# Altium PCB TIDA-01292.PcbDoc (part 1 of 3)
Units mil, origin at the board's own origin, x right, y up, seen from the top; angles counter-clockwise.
Board outline 6102.36 x 3543.31 mil, 2 copper layers (Top Layer, Bottom Layer), stack 64.8 mil thick; 118 components, 43 nets, 376 pads, 3910 vias.
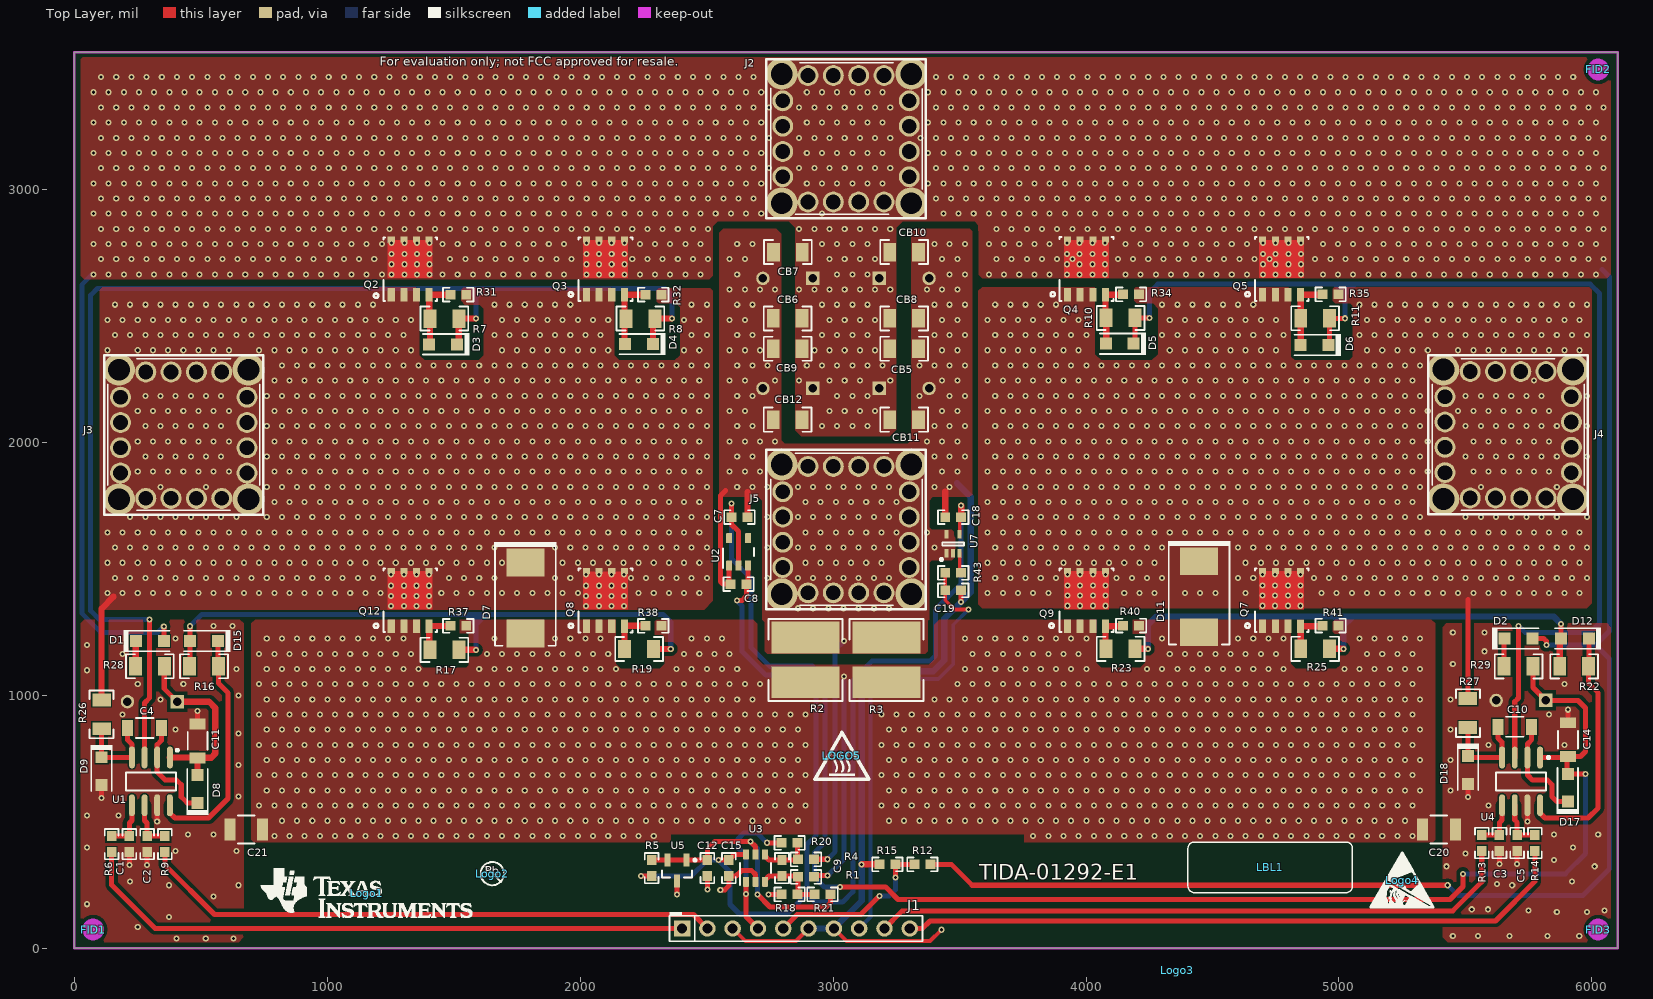
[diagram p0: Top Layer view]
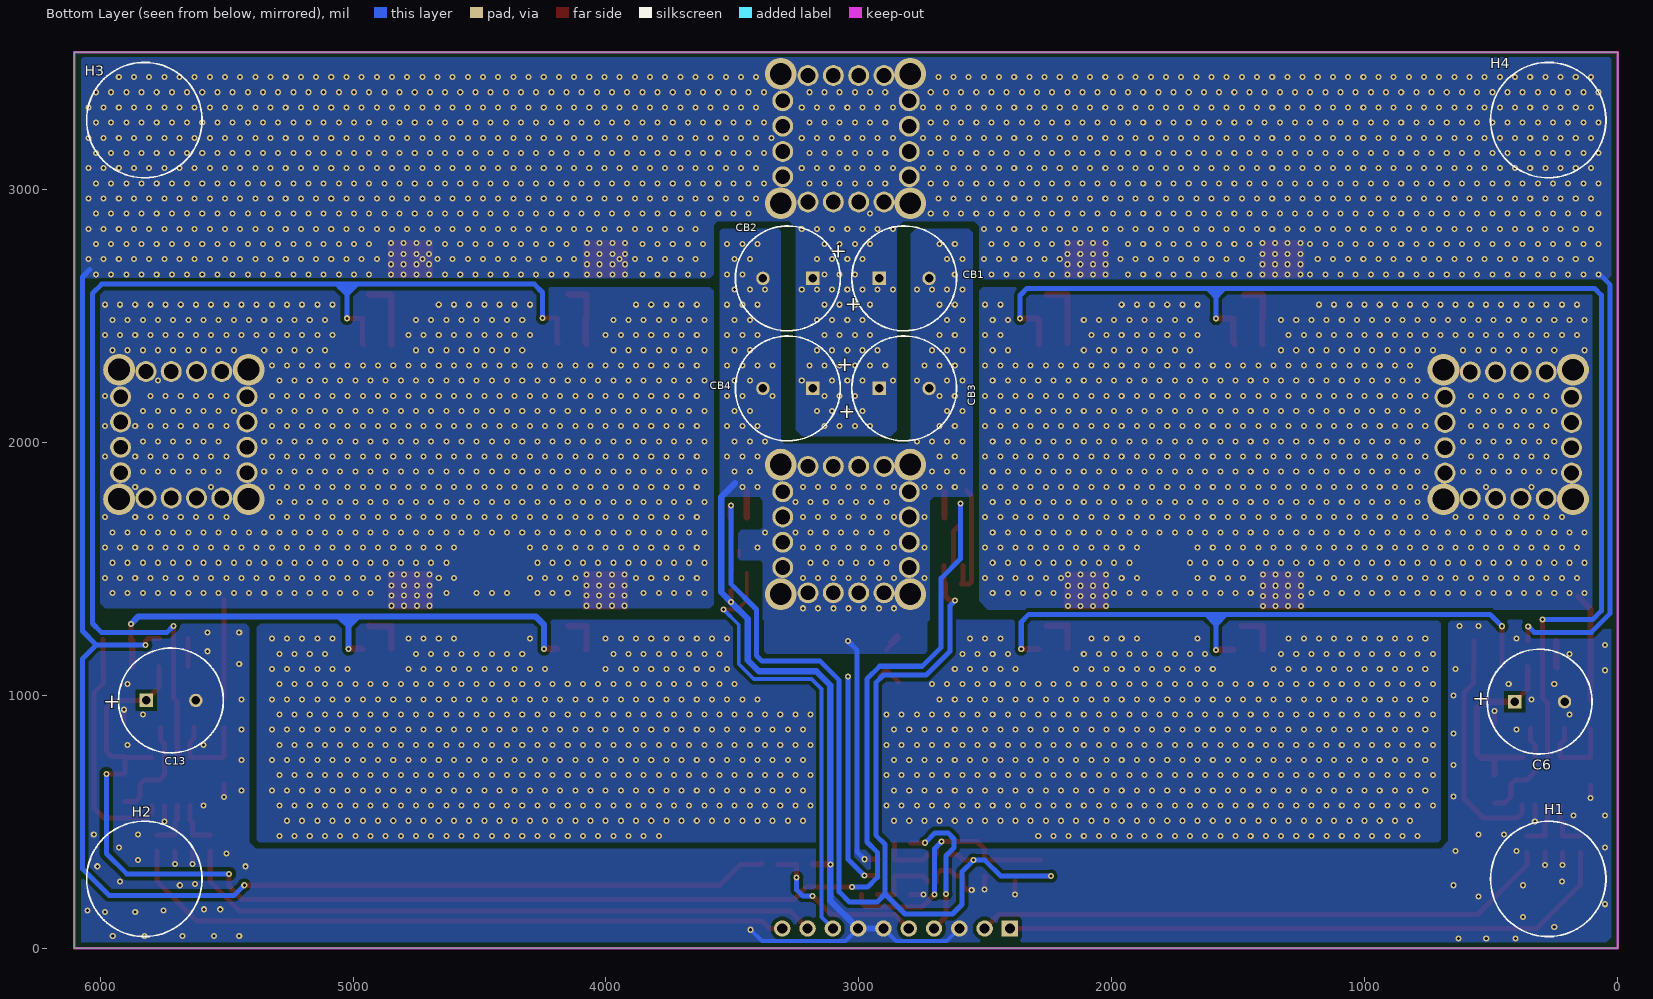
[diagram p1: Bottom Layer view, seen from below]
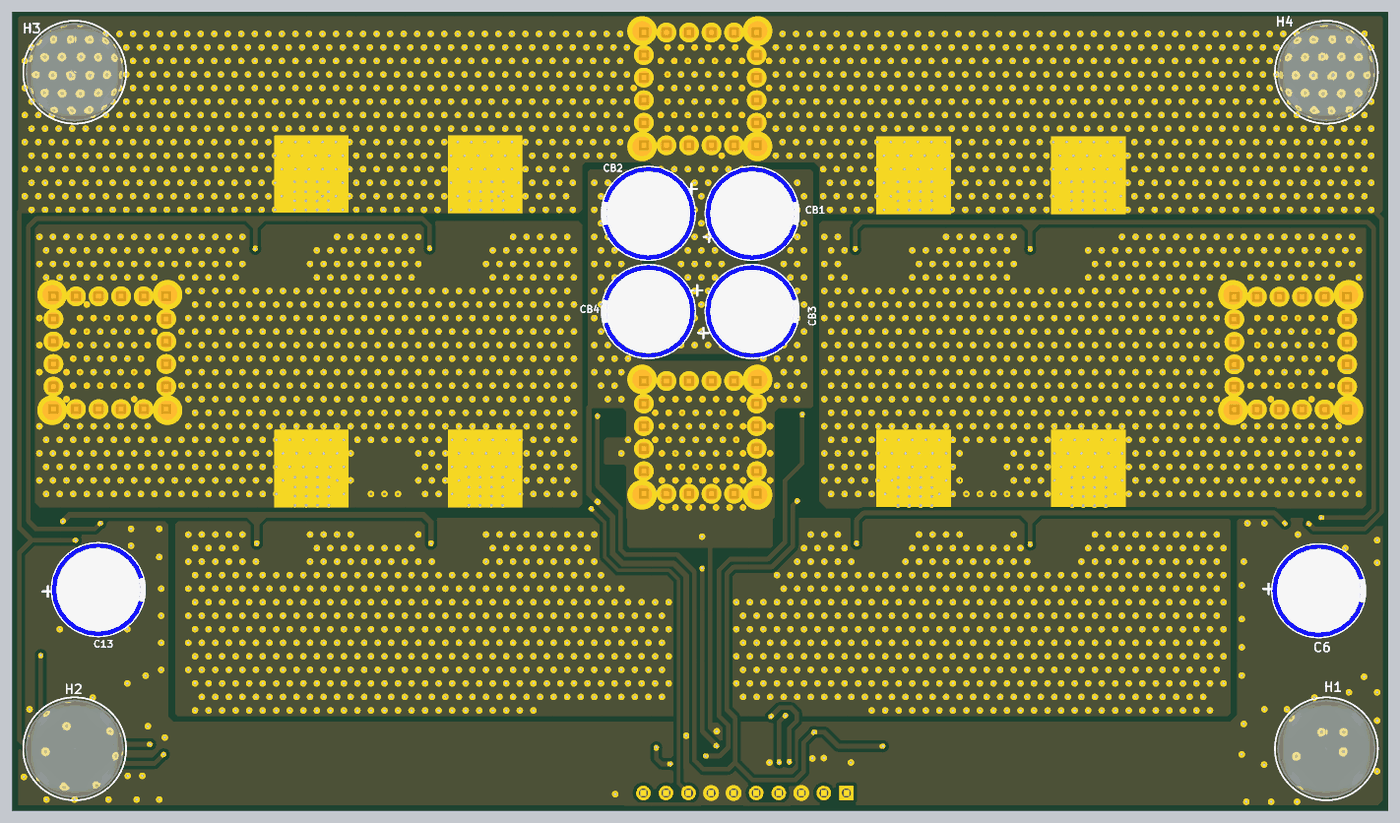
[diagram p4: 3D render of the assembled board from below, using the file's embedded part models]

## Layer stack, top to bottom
Top Solder: solder mask 0.4, Solder Resist, Dk 3.5
Top Layer: signal copper 2.8
Dielectric1: core 59.2, FR-4 High Tg, Dk 4.8
Bottom Layer: signal copper 2.8
Bottom Solder: solder mask 0.4, Solder Resist, Dk 3.5

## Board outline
0,0 6102.36,0 6102.36,3543.31 0,3543.31

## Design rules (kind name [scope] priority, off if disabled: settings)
AcuteAngle [All] p1: minimum=4.50000000000000E+0001 checktracksonly=FALSE
AssemblyTestPointUsage [All] p1: valid=2
Clearance Clearance_HS_Pads [InPadClass('HS_Pads') vs InPolygon] p1: gap=25
Clearance Clearance_Keepouts [OnCopper And InPolygon vs IsKeepOut] p2: gap=15
Clearance Clearance_Poly [InPolygon] p3: gap=15 except(6: SMDPad-Poly; 25: Poly-Poly)
Clearance [All] p4: gap=7.87
ComponentClearance ComponentClearance_MountingHoles_FiducialMarks [InComponentClass('Mounting Holes') vs InComponentClass('FiducialMark')] p1: gap=10 collisioncheckmode=3 verticalgap=10 showdistances=FALSE
ComponentClearance ComponentClearance_Shunt [InComponentClass('Header') vs InComponentClass('Shunt')] p2: gap=0 collisioncheckmode=3 verticalgap=0 showdistances=FALSE
ComponentClearance ComponentClearance_Logo [InComponentClass('Logo')] p3: gap=10 collisioncheckmode=3 verticalgap=10 showdistances=FALSE
ComponentClearance ComponentClearance_ScrewToNut [(HasFootprint('NY PMS 440 0025 PH')) vs (HasFootprint('Keystone_1902C'))] p4: gap=5 collisioncheckmode=3 verticalgap=10 showdistances=FALSE
ComponentClearance ComponentClearance_MountingHoles [InComponentClass('Mounting Holes')] p5: gap=50 collisioncheckmode=3 verticalgap=100000 showdistances=FALSE
ComponentClearance ComponentClearance_SmallPassives [HasFootprint('0201*') or HasFootprint('0402*') or HasFootprint('0508') or HasFootprint('0603*') or HasFootprint('0612') or HasFootprint('0805*') or HasFootprint('0815*') or HasFootprint('0830*') or HasFootprint('1206*') or HasFootprint('1210*') or HasFootprint('1808*') or HasFootprint('1812*') or HasFootprint('1825*') or HasFootprint('2010*') or HasFootprint('2220*') or HasFootprint('2225*') or HasFootprint('2512*') or HasFootprint('2728*') or HasFootprint('3518*') vs HasFootprint('0201*') or HasFootprint('0402*') or HasFootprint('0508') or HasFootprint('0603*') or HasFootprint('0612') or HasFootprint('0805*') or HasFootprint('0815*') or HasFootprint('0830*') or HasFootprint('1206*') or HasFootprint('1210*') or HasFootprint('1808*') or HasFootprint('1812*') or HasFootprint('1825*') or HasFootprint('2010*') or HasFootprint('2220*') or HasFootprint('2225*') or HasFootprint('2512*') or HasFootprint('2728*') or HasFootprint('3518*')] p6: gap=14.96 collisioncheckmode=3 verticalgap=10 showdistances=FALSE
ComponentClearance ComponentClearance_THtoSMT [IsThruComponent vs IsSMTComponent] p7: gap=10 collisioncheckmode=3 verticalgap=10 showdistances=FALSE
ComponentClearance ComponentClearance_THtoTH [IsThruComponent vs IsThruComponent] p8: gap=10 collisioncheckmode=3 verticalgap=10 showdistances=FALSE
ComponentClearance [All] p9: gap=10 collisioncheckmode=3 verticalgap=10 showdistances=FALSE
DiffPairsRouting [All] p1: maxlimit=100 minlimit=10 mostfreqgap=10 toplayer_minwidth=15 toplayer_maxwidth=15 toplayer_prefwidth=15 bottomlayer_minwidth=15 bottomlayer_maxwidth=15 bottomlayer_prefwidth=15 maxuncoupledlength=1000
FabricationTestPointUsage TestPointUsage [All] p1: valid=2 allowmultiple=FALSE
FabricationTestpoint Testpoint [All] p1: side=3 testpointundercomponent=TRUE minsize=40 maxsize=100 preferedsize=60 minholesize=0 maxholesize=40 preferedholesize=32 testpointgrid=1 allowsidetop=TRUE allowsidebottom=TRUE usegrid=TRUE gridtolerance=0.01
FanoutControl Fanout_LCC [IsLCC] p1: bgadir=Out bgaviamode=Centered fanoutstyle=Auto fanoutdirection=Alternating viagrid=1 // Fanout_LCC (Default Rule)
FanoutControl Fanout_BGA [IsBGA] p2: bgadir=Out bgaviamode=Centered fanoutstyle=Auto fanoutdirection=Alternating viagrid=1 // Fanout_BGA (Default Rule)
FanoutControl Fanout_Default [All] p4: bgadir=Out bgaviamode=Centered fanoutstyle=Auto fanoutdirection=Alternating viagrid=1 // Fanout_Default (Default Rule)
FanoutControl Fanout_Small [(CompPinCount < 5)] p5: bgadir=Out bgaviamode=Centered fanoutstyle=Auto fanoutdirection=OutThenIn viagrid=1 // Fanout_Small (Default Rule)
HoleSize [All] p1: absolutevalues=TRUE maxlimit=251 minlimit=7.87 maxpercent=80.000 minpercent=20.000
MinimumAnnularRing MinimumAnnularRing_ThermalPadVias [IsVia and InAnyComponent] p1: minimumring=5.91
MinimumAnnularRing [All] p2: minimumring=6
MinimumSolderMaskSliver MinimumSolderMaskSliver_Logo [InComponentClass('Logo') vs InComponentClass('Logo')] p1: minsoldermaskwidth=0.7
MinimumSolderMaskSliver [All] p2: minsoldermaskwidth=3.94
PlaneConnect [All] p1: planeconnectstyle=Relief reliefexpansion=10 reliefentries=4 reliefconductorwidth=10 reliefairgap=10
PolygonConnect [All] p1: connectstyle=Direct reliefconductorwidth=10 reliefentries=4 polygonreliefangle="90 Angle" airgapwidth=10
RoutingVias ThermalPadVias [IsVia and InAnyComponent] p1: holewidth=7.87 width=19.68 viastyle="Through Hole" minholewidth=7.87 minwidth=19.68 maxholewidth=12.99 maxwidth=23.62
RoutingVias [All] p2: holewidth=16 width=34 viastyle="Through Hole" minholewidth=12 minwidth=24 maxholewidth=40 maxwidth=65
SilkToBoardRegionClearance [Not ((IsComment or IsDesignator) And (Hide <> 'False')) and not InRegion(1000,500,4000,800)] p1:
SilkToSilkClearance SilkToSilkClearance_Pb-FreeLogo [(HasFootprint('Pb-Free_Overlay_Medium') OR HasFootprint('Pb-Free_Overlay_Small')) vs (HasFootprint('Pb-Free_Overlay_Medium') OR HasFootprint('Pb-Free_Overlay_Small'))] p1: silktosilkclearance=0
SilkToSilkClearance [All] p2: silktosilkclearance=4
SilkToSolderMaskClearance SilkToComponentPadClearance [IsPad and InAnycomponent] p1: minsilkscreentomaskgap=5 clearancetoexposedcopper=TRUE
SilkToSolderMaskClearance "Silk to Solder Mask Opening" [All] p2: minsilkscreentomaskgap=4 clearancetoexposedcopper=FALSE
SolderMaskExpansion [All] p1: expansion=2.5
Width [All] p1: maxlimit=100 minlimit=6 preferedwidth=10 checkconnectedcopper=TRUE
15 further rules are at their usual default settings.

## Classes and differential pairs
component class Label: LBL1
component class AssemblyNote: ZZ1 ZZ2 ZZ3 ZZ4
component class FiducialMark: FID1 FID2 FID3
component class TIDA-01292_EVM_Hardware: FID1 FID2 FID3 H1 H2 H3 H4 LBL1 Logo1 Logo2 Logo3 Logo4 LOGO5 ZZ1 ZZ2 ZZ3 ZZ4
component class Logo: Logo1
component class TIDA-01292_Sheet1: C1 C2 C3 C4 C5 C6 C7 C8 C9 C10 C11 C12 C13 C14 C15 C18 C19 C20 C21 CB1 CB2 CB3 CB4 CB5 CB6 CB7 CB8 CB9 CB10 CB11 CB12 D1 D2 D3 D4 D5 D6 D7 D8 D9 D11 D12 D15 D17 D18 J1 J2 J3 J4 J5 Q2 Q3 Q4 Q5 Q7 Q8 Q9 Q12 R1 R2 R3 R4 R5 R6 R7 R8 R9 R10 R11 R12 R13 R14 R15 R16 R17 R18 R19 R20 R21 R22 R23 R25 R26 R27 R28 R29 R31 R32 R34 R35 R37 R38 R40 R41 R43 U1 U2 U3 U4 U5 U7
component class Header: J1

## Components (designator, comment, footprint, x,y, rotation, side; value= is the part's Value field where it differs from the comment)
C1 "885012206034" 0603 218.15,412.35 r270 top
C2 "885012206034" 0603 288.15,412.35 r270 top
C3 "885012206034" 0603 5634.61,417.01 r270 top
C4 "C3216X5R1H106K160AB" 1206_180 278.15,871.8 r180 top
C5 "885012206034" 0603 5704.61,417.01 r270 top
C6 "35ZLG470MEFC10X20" ZLH_1000x2300 308.98,975.85 r180 bottom
C7 "C0603C105K3RACTU" 0603 2630,1705 r0 top
C8 "C0603C105K3RACTU" 0603 2626.65,1440.85 r180 top
C9 "C0603C105K3RACTU" 0603 2798.15,317.74 r90 top
C10 "C3216X5R1H106K160AB" 1206_180 5695,876.46 r180 top
C11 "C3216X5R1H106K160AB" 1206_180 487.64,820.85 r90 top
C12 "C0603C105K3RACTU" 0603 2503.15,317.74 r270 top
C13 "35ZLG470MEFC10X20" ZLH_1000x2300 5720,980.51 r180 bottom locked
C14 "C3216X5R1H106K160AB" 1206_180 5905.36,825.51 r90 top
C15 "C0603C105K3RACTU" 0603 2588.15,317.74 r270 top
C18 "C0603C105K3RACTU" 0603 3475,1705 r180 top
C19 "C0603C105K3RACTU" 0603 3475,1415.78 r0 top
C20 "1210YD106KAT2A" 1210_280 5395,470 r0 top
C21 "1210YD106KAT2A" 1210_280 680,470 r180 top
CB1 "25ZLH1000MEFC10X23" ZLH_1000x2300 2821.15,2649.08 r180 bottom
CB2 "25ZLH1000MEFC10X23" ZLH_1000x2300 3281.15,2649.08 r0 bottom
CB3 "25ZLH1000MEFC10X23" ZLH_1000x2300 2821.15,2214.08 r180 bottom
CB4 "25ZLH1000MEFC10X23" ZLH_1000x2300 3281.15,2214.08 r0 bottom
CB5 "12063C105KAT2A" 1206 3281.15,2370.85 r0 top
CB6 "12063C105KAT2A" 1206 2820.59,2490.85 r180 top
CB7 "12063C105KAT2A" 1206 2821.15,2753.18 r180 top
CB8 "12063C105KAT2A" 1206 3281.15,2490.85 r0 top
CB9 "12063C105KAT2A" 1206 2820.59,2370.85 r180 top
CB10 "12063C105KAT2A" 1206 3281.15,2753.18 r0 top
CB11 "12063C105KAT2A" 1206 3281.15,2090.85 r0 top
CB12 "12063C105KAT2A" 1206 2820.59,2090.85 r180 top
D1 "MBR1020VL" SOD-123F 298.98,1215.6 r0 top
D2 "MBR1020VL" SOD-123F 5710,1225.51 r0 top
D3 "MBR1020VL" SOD-123F 1458.39,2388.4 r180 top
D4 "MBR1020VL" SOD-123F 2233.39,2389.3 r180 top
D5 "MBR1020VL" SOD-123F 4133.3,2391.09 r180 top
D6 "MBR1020VL" SOD-123F 4903.3,2386.09 r180 top
D7 "5.0SMDJ20A" SMC 1783.39,1385.85 r270 top
D8 "MBR1020VL" SOD-123F 487.13,630.85 r90 top
D9 "MBR1020VL" SOD-123F 108.15,700.85 r270 top
D11 "5.0SMDJ20A" SMC 4446.79,1390.52 r270 top
D12 "MBR1020VL" SOD-123F 5932.72,1225.51 r180 top
D15 "MBR1020VL" SOD-123F 513.15,1215.85 r180 top
D17 "MBR1020VL" SOD-123F 5905,635.51 r90 top
D18 "MBR1020VL" SOD-123F 5510,705.51 r270 top
FID1 "Fiducial" Fiducial10-20 75,75 r0 top
FID2 "Fiducial" Fiducial10-20 6025,3475 r0 top
FID3 "Fiducial" Fiducial10-20 6025,75 r0 top
H1 "SJ-5303 (CLEAR)" Bumpon_SJ5003Transparent 275,275 r180 bottom
H2 "SJ-5303 (CLEAR)" Bumpon_SJ5003Transparent 5825,275 r180 bottom
H3 "SJ-5303 (CLEAR)" Bumpon_SJ5003Transparent 5825,3275 r180 bottom
H4 "SJ-5303 (CLEAR)" Bumpon_SJ5003Transparent 275,3275 r180 bottom
J1 "TSW-110-07-G-S" TSW-110-07-G-S 2853.15,79 r0 top
J2 "7461090" "7461090_Chemical Surface"#1 3051.18,3201 r0 top
J3 "7461090" "7461090_Chemical Surface"#2 174.62,2031.19 r0 top
J4 "7461090" "7461090_Chemical Surface"#1 5668.91,2031.19 r0 top
J5 "7461090" "7461090_Chemical Surface"#1 3051.18,1655.85 r0 top
LBL1 "Size: 0.65\" x 0.20 \"" Label_650x200 4728.15,320.85 r0 top
Logo1 "Texas Instruments" TI_Stacked_Overlay_Small 1156.15,219 r0 top
Logo2 "Pb-Free Symbol" Pb-Free_Overlay_Small 1653.15,295.85 r0 top
Logo3 "FCC disclaimer" FCC_disclaimer 4361.15,-86.3 r90 top
Logo4 "ESD Susceptible" ESD_Overlay_Medium 5250,270 r0 top
LOGO5 "CAUTION HOT SURFACE" IEC_HotSurface_Small 3035,762 r0 top
Q2 "CSD17573Q5B" TRANS_NexFET_Q5B 1328.38,2693.33 r90 top
Q3 "CSD17573Q5B" TRANS_NexFET_Q5B 2100.17,2693.33 r90 top
Q4 "CSD17573Q5B" TRANS_NexFET_Q5B 4001.83,2693.74 r90 top
Q5 "CSD17573Q5B" TRANS_NexFET_Q5B 4773.62,2693.74 r90 top
Q7 "CSD17573Q5B" TRANS_NexFET_Q5B 4773.62,1383.61 r90 top
Q8 "CSD17573Q5B" TRANS_NexFET_Q5B 2100.17,1383.19 r90 top
Q9 "CSD17573Q5B" TRANS_NexFET_Q5B 4001.83,1383.61 r90 top
Q12 "CSD17573Q5B" TRANS_NexFET_Q5B 1328.38,1383.61 r90 top
R1 "RC0603JR-070RL" 0603 2893.15,282.74 r180 top
R2 "CSS2725FTL500" CSS2725_0005 2891.15,1140.85 r270 top
R3 "CSS2725FTL500" CSS2725_0005 3211.15,1140.85 r270 top
R4 "RC0603JR-070RL" 0603 2893.15,352.74 r180 top
R5 "CRCW06032K00FKEA" 0603 2283.15,317.74 r270 top
R6 "CRCW0603100RFKEA" 0603 148.15,412.35 r90 top
R7 "CRCW12063R00JNEA" 1206 1463.38,2490.26 r180 top
R8 "CRCW12063R00JNEA" 1206 2238.39,2490.26 r180 top
R9 "CRCW0603100RFKEA" 0603 358.15,412.35 r90 top
R10 "CRCW12063R00JNEA" 1206 4136.58,2492.73 r180 top
R11 "CRCW12063R00JNEA" 1206 4905.99,2491.42 r180 top
R12 "CRCW06030000Z0EA" 0603 3353.15,332.74 r0 top
R13 "CRCW0603100RFKEA" 0603 5564.61,417.01 r90 top
R14 "CRCW0603100RFKEA" 0603 5774.61,417.01 r90 top
R15 "CRCW06030000Z0EA" 0603 3214.65,332.74 r0 top
R16 "CRCW12063R00JNEA" 1206 513.15,1115.6 r180 top
R17 "CRCW12063R00JNEA" 1206 1463.38,1180.68 r180 top
R18 "RC0603JR-070RL" 0603 2828.15,214 r180 top
R19 "CRCW12063R00JNEA" 1206 2233.39,1183.97 r180 top
R20 "RC0603JR-070RL" 0603 2828.15,417.74 r0 top
R21 "RC0603JR-070RL" 0603 2958.15,214 r180 top
R22 "CRCW12063R00JNEA" 1206 5930,1115.26 r180 top
R23 "CRCW12063R00JNEA" 1206 4136.58,1184.38 r180 top
R25 "CRCW12063R00JNEA" 1206 4905.99,1184.38 r180 top
R26 "CRCW12063R00JNEA" 1206 108.15,925.85 r90 top
R27 "CRCW12063R00JNEA" 1206 5510,930.51 r90 top
R28 "CSR1206FK1R00" 1206 298.98,1115.6 r0 top
R29 "CSR1206FK1R00" 1206 5710,1115.26 r0 top
R31 "CRCW060322K0JNEA" 0603 1518.39,2584.69 r180 top
R32 "CRCW060322K0JNEA" 0603 2289.39,2584.69 r180 top
R34 "CRCW060322K0JNEA" 0603 4178.3,2586.09 r180 top
R35 "CRCW060322K0JNEA" 0603 4966.99,2585.83 r180 top
R37 "CRCW060322K0JNEA" 0603 1518.39,1275.03 r180 top
R38 "CRCW060322K0JNEA" 0603 2289.39,1275.68 r180 top
R40 "CRCW060322K0JNEA" 0603 4178.3,1276.09 r180 top
R41 "CRCW060322K0JNEA" 0603 4966.99,1276.09 r180 top
R43 "CRCW06030000Z0EA" 0603 3475,1485 r180 top
U1 "LM5101AMX" M08A_N 303.15,660.85 r270 top
U2 "TLV70433DBVR" DBV0005A_N 2626.65,1567.93 r90 top
U3 "INA181A1IDBVR" DBV0006A_N 2693.15,317.74 r90 top
U4 "LM5101AMX" M08A_N 5720,660.51 r270 top
U5 "LMV431BIMF/NOPB" MF03A_N 2383.15,307.74 r270 top
U7 "LM20CIM7X" MAA05A_N 3475,1600 r90 top
ZZ1 "This Assembly Note is for PCB labels only" AssemblyNoteLabel 168.15,3947 r0 top
ZZ2 "These assemblies are ESD sensitive, ESD precautions shall be observed." AssemblyNote 168.15,3856.11 r0 top
ZZ3 "These assemblies must be clean and free from flux and all contaminants. Use of no clean flux is not acceptable." AssemblyNote 168.15,3767.56 r0 top
ZZ4 "These assemblies must comply with workmanship standards IPC-A-610 Class 2, unless otherwise specified." AssemblyNote 168.15,3679 r0 top

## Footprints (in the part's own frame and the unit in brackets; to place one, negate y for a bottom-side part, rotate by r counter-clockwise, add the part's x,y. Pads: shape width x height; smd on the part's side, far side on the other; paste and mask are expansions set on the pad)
0603 [mm] "0603 from SM-752 data"
  rect 1x0.95 smd: 1(-0.8,0) 2(0.8,0)
  silkscreen extent -1.52,-0.69 1.52,0.69, body extent -0.87,-0.47 0.87,0.47, height 1
1206 [mm] "1206 from SM-752 data"
  rect 1.3x1.85 smd: 1(-1.45,0) 2(1.45,0)
  silkscreen extent -2.4,-1.21 2.4,1.21, body extent -1.7,-0.9 1.7,0.9, height 1.35
1206_180 [mm]
  rect 1.1x1.6 smd: 1(-1.7,0) 2(1.7,0)
  silkscreen extent -0.9,-1 0.9,1, body extent -1.75,-0.95 1.75,0.95, height 1.8
1210_280 [mm] "SMD, 2-Leads, Body 3.6x2.8mm, Height 2.8mm"
  rect 1.1x2.2 smd: 1(-1.65,0) 2(1.65,0)
  silkscreen extent -0.84,-1.4 0.84,1.4, body extent -1.8,-1.4 1.8,1.4, height 2.8
"7461090_Chemical Surface"#1 [mm] "M5, thr 6mm"
  round 2.1 hole 1.475: 1(-6.35,-6.35) 1(-6.35,-3.81) 1(-6.35,-1.27) 1(-6.35,1.27) 1(-6.35,3.81) 1(-6.35,6.35) 1(-3.81,-6.35) 1(-3.81,6.35) 1(-1.27,-6.35) 1(-1.27,6.35) 1(1.27,-6.35) 1(1.27,6.35) 1(3.81,-6.35) 1(3.81,6.35) 1(6.35,-6.35) 1(6.35,-3.81) 1(6.35,-1.27) 1(6.35,1.27) 1(6.35,3.81) 1(6.35,6.35)
  silkscreen extent -8,-8 8,8, body extent -8,-8 8,8, height 13.6
"7461090_Chemical Surface"#2 [mm] "M8, thr 13.5mm"
  round 2.1 hole 1.475: 1(0.213,-6.395) 1(0.213,-3.855) 1(0.213,-1.315) 1(0.213,1.225) 1(0.213,3.765) 1(0.213,6.305) 1(2.753,-6.395) 1(2.753,6.305) 1(5.293,-6.395) 1(5.293,6.305) 1(7.833,-6.395) 1(7.833,6.305) 1(10.373,-6.395) 1(10.373,6.305) 1(12.913,-6.395) 1(12.913,-3.855) 1(12.913,-1.315) 1(12.913,1.225) 1(12.913,3.765) 1(12.913,6.305)
  silkscreen extent -1.44,-8.04 14.56,7.96, body extent -1.44,-8.04 14.56,7.96, height 13.6
AssemblyNote [mil] "Assembly Note"
AssemblyNoteLabel [mil] "Assembly Note for PCB Labels"
Bumpon_SJ5003Transparent [mil] "3M Hemispherical Bumpon transparent"
  round 1 on Mech4: 0(0,0)
  silkscreen extent -228,-228 228,228, body extent -219,-219 219,219, height 197
CSS2725_0005 [mm] "STACKPOLE ELECTRONICS"
  rect 3.18x6.86 smd: 1(-2.25,0) 2(2.25,0)
  silkscreen extent -4.13,-3.7 4.13,3.7, body extent -3.53,-3.35 3.53,3.35, height 1.24
DBV0005A_N [mm] "SOT23, 5-Leads, Body 2.9x1.6mm, Pitch 0.95mm, Lead Span 2.8mm, IPC Medium Density"
  rrect17% 1x0.6 smd: 1(-1.375,0.95) 2(-1.375,0) 3(-1.375,-0.95) 4(1.375,-0.95) 5(1.375,0.95)
  silkscreen extent -1.63,-1.55 0.38,1.55, body extent -1.42,-1.46 1.42,1.46, height 1.09
DBV0006A_N [mm] "SOT23, 6-Leads, Body 2.9x1.6mm, Pitch 0.95mm, Lead Span 2.8mm, IPC Medium Density"
  rrect17% 1x0.6 smd: 1(-1.375,0.95) 2(-1.375,0) 3(-1.375,-0.95) 4(1.375,-0.95) 5(1.375,0) 6(1.375,0.95)
  silkscreen extent -1.68,-1.55 0.5,1.55, body extent -1.42,-1.46 1.42,1.46, height 1.12
ESD_Overlay_Medium [mil]
  silkscreen extent -127,-109 125,110
FCC_disclaimer [mil]
Fiducial10-20 [mm]
  round 1 smd mask+0.5: 1(0,0)
  Top Layer keep-out circle w1.178: c0,0 r0.5
IEC_HotSurface_Small [mil]
  silkscreen extent -107,-93 107,92
Label_650x200 [mil] "Thermal Transfer Label"
  silkscreen extent -325,-100 325,100, body extent -325,-100 325,100, height 1
M08A_N [mm] "SOIC, 8-Leads, Body 4.9x3.9mm, Pitch 1.27mm, IPC Medium Density"
  oval 2.2x0.6 smd: 1(-2.4,1.905) 2(-2.4,0.635) 3(-2.4,-0.635) 4(-2.4,-1.905) 5(2.4,-1.905) 6(2.4,-0.635) 7(2.4,0.635) 8(2.4,1.905)
  silkscreen extent -3.25,-2.5 0.9,2.77, body extent -2,-2.5 2,2.5, height 1.75
MAA05A_N [mm] "SOT353, 5-Leads, Body 2x1.3mm, Pitch 0.65mm, Lead Span 2.1mm, IPC Medium Density"
  rect 0.85x0.4 smd: 1(-0.95,0.65) 2(-0.95,0) 3(-0.95,-0.65) 4(0.95,-0.65) 5(0.95,0.65)
  silkscreen extent -1.71,-1.1 0.15,1.31, body extent -0.7,-1.1 0.7,1.1, height 1.1
MF03A_N [mm] "SOT23, 3-Leads, Body 2.9x1.3mm, Pitch 0.95mm, Lead Span 2.4mm, IPC Medium Density"
  rect 1.3x0.6 smd: 1(-1.05,0.95) 2(-1.05,-0.95) 3(1.05,0)
  silkscreen extent -1.17,-1.5 0.7,1.93, body extent -0.7,-1.5 0.7,1.5, height 1.12
Pb-Free_Overlay_Small [mil]
  silkscreen extent -46,-46 46,46
SMC [mil] "Molded Diode, 2-Leads, Body 6.9x5.8mm, IPC Medium Density, based on OnSemi component dimensions and land patterns"
  rect 110x150 smd: 1(-140.49,0) 2(140.49,0)
  silkscreen extent -221,-124 189,123, body extent -156,-116 156,116, height 91
SOD-123F [mm] "NXP recommended land pattern"
  rect 1.2x1.2 smd paste-0.05: 1(-1.4,0) 2(1.4,0)
  silkscreen extent -2.64,-1.12 2.01,1.12, body extent -1.8,-0.85 1.8,0.85, height 1.2
TI_Stacked_Overlay_Small [mil]
  silkscreen extent -418,-98 418,98
TRANS_NexFET_Q5B [mm] "TI recommended land pattern (nominal) November 2012"
  rect 1.372x0.71 smd paste-0.4: 1(-2.776,1.905) 2(-2.776,0.635) 3(-2.776,-0.635) 4(-2.776,-1.905)
  rect 0.59x0.71 smd paste-0.3: 5(2.776,-1.905) 6(2.776,-0.635) 7(2.776,0.635) 8(2.776,1.905)
  Top Layer region: -1.106,-2.26 2.744,-2.26 2.744,2.26 -1.106,2.26
  silkscreen extent -3.38,-2.7 3,2.7, body extent -3.23,-2.55 2.87,2.55, height 1.06
TSW-110-07-G-S [mm] "Samtec 100mil, 1x10, 230 mil above insulator"
  rrect6% 1.65x1.65 hole 1.016: 1(-11.43,0)
  round 1.65 hole 1.016: 2(-8.89,0) 3(-6.35,0) 4(-3.81,0) 5(-1.27,0) 6(1.27,0) 7(3.81,0) 8(6.35,0) 9(8.89,0) 10(11.43,0)
  silkscreen extent -12.7,-1.27 12.7,1.65, body extent -12.7,-1.27 12.7,1.27, height 8.38
ZLH_1000x2300 [mm] "TH, 2-Leads, Dia 10mm, Pin Spacing 5mm"
  rect 1.35x1.35 hole 0.85: 1(-2.5,0)
  round 1.35 hole 0.85: 2(2.5,0)
  silkscreen extent -5.26,-5.26 5.26,5.26, body extent -5.25,-5.25 5.26,5.25, height 25.01

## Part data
C1 C2 C3 C5: "CAP, CERM, 1000 pF, 16 V, +/- 10%, X7R, 0603"
C4 C10 C11 C14: "CAP, CERM, 10 µF, 50 V, +/- 10%, X5R, 1206"
C6 C13: library part 25ZLH1000MEFC10X23, "CAP ALUM 470UF 20% 35V RADIAL"
C7 C8 C9 C12 C15 C18 C19: "CAP, CERM, 1 µF, 25 V, +/- 10%, X7R, 0603"
C20 C21: "CAP, CERM, 10 µF, 16 V, +/- 10%, X5R, 1210"
CB1 CB2 CB3 CB4: "CAP, AL, 1000 µF, 25 V, +/- 20%, 0.018 ohm, TH"
CB5 CB6 CB7 CB8 CB9 CB10 CB11 CB12: "CAP, CERM, 1 µF, 25 V, +/- 10%, X7R, 1206"
D1 D2 D3 D4 D5 D6 D8 D9 D12 D15 D17 D18: "Diode, Schottky, 20 V, 1 A, SOD-123F"
D7 D11: "Diode, TVS, Uni, 20 V, 5000 W, SMC"
FID1 FID2 FID3: "Fiducial mark.  There is nothing to buy or mount."
H1 H2 H3 H4: "Bumpon, Hemisphere, 0.44 X 0.20, Clear"
J1: "Header, 100mil, 10x1, Gold, TH"
J2 J3 J4 J5: "REDCUBE PRESS-FIT with internal thread, circumference WP-BUCF, M8, 13.5 mm"
LBL1: library part THT-14-423-10, "Thermal Transfer Printable Labels, 0.650\" W x 0.200\" H - 10,000 per roll"
Logo1: library part TI_Logo, "Texas Instrument Corporate Signature"
Logo2: library part Pb-Free
Logo3: library part FCC_disclaimer, "FCC_disclaimer"
Logo4: library part ESD_Susceptible, "ESD Susceptible Symbol"
LOGO5: library part IEC_HotSurface, "IEC 61010-1 Hot Surface Warning"
Q2 Q3 Q4 Q5 Q7 Q8 Q9 Q12: "MOSFET, N-CH, 30 V, 100 A, SON 5x6mm"
R1 R4 R12 R15 R18 R20 R21 R43: "RES, 0, 5%, 0.1 W, 0603"
R2 R3: "RES, 0.0005, 1%, 4 W, RES_2725"
R5: "RES, 2.00 k, 1%, 0.1 W, 0603"
R6 R9 R13 R14: "RES, 100, 1%, 0.1 W, 0603"
R7 R8 R10 R11 R16 R17 R19 R22 R23 R25 R26 R27: "RES, 3.0, 5%, 0.25 W, 1206"
R28 R29: "RES, 1.00, 1%, 0.5 W, 1206"
R31 R32 R34 R35 R37 R38 R40 R41: "RES, 22 k, 5%, 0.1 W, 0603"
U1 U4: "3A High Voltage High-Side and Low-Side Gate Driver, 8-pin Narrow SOIC"
U2: "Single Output LDO, 150 mA, Fixed 3.3 V Output, 2.5 to 24 V Input, with Ultra-Low IQ, 5-pin SOT-23 (DBV), -40 to 125 degC, Green (RoHS & no Sb/Br)"
U3: "Bidirectional, Low- and High-Side Measurement, Multichannel, Voltage Output, Current-Sense Amplifier, DBV0006A (SOT-23-6)"
U5: "Low-Voltage (1.24V) Adjustable Precision Shunt Regulators, 3-pin SOT-23, Pb-Free"
U7: "Temperature Sensor Analog, Local -55°C ~ 130°C 11.77mV/°C SC-70-5"
ZZ1: library part AssemblyNoteLabel
ZZ2 ZZ3 ZZ4: library part AssemblyNote

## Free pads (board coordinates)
  round 125.98 hole 86.61: 1(177.05,1776.07) 1(177.05,2287.88) 1(688.86,1776.07) 1(688.86,2287.88) 1(2797.2,1401.03) 1(2797.2,1912.84) 1(2797.2,2946.03) 1(2797.2,3457.84) 1(3309.01,1401.03) 1(3309.01,1912.84) 1(3309.01,2946.03) 1(3309.01,3457.84) 1(5412.97,1776.37) 1(5412.97,2288.18) 1(5924.78,1776.37) 1(5924.78,2288.18)

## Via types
v1: diameter 24, hole 12, Top Layer to Bottom Layer, 3910 vias

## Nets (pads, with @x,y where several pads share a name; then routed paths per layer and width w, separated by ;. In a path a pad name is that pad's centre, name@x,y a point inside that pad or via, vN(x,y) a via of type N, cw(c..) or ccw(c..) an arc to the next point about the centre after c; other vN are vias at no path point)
3.3V: C8.1 C15.1 C18.1 R5.2 U2.3 U3.6 U7.4 | length 4769.7
  Top Layer w15: U7.4@3500.59,1637.4 C18.1@3500.59,1699.09
  Top Layer w20: v1(2241.46,286.24) R5.2@2283.15,286.24 ; v1(2546.46,349.24) C15.1@2588.15,349.24 2610.79,371.87 U3.6@2655.75,371.87 ; v1(2620,1375) 2640,1375 2658.15,1393.15 C8.1@2658.15,1440.85 2664.06,1446.76 U2.3@2664.06,1513.79
  Top Layer w25: C18.1@3506.5,1705 v1(3506.5,1751.5)
  Bottom Layer w20: v1(2241.46,286.24) 2439.39,286.24 2502.39,349.24 v1(2546.46,349.24) 2592.15,303.54 2592.15,174 2630.15,136 2818.1,136 2897.13,215.02 ; v1(2620,1375) 2640,1355 2640,1175 2734.15,1080.85 2903.15,1080.85 2933.15,1050.85 2933.15,447.98 2897.13,411.95 2897.13,215.02 ; v1(3506.5,1751.5) 3506.5,1441.5 3405,1340 3405,1157.7 3383.15,1135.85 3153.15,1135.85 3078.15,1060.85 3078.15,224 3038.15,184 2928.15,184 2897.13,215.02
BOUT: J1.4 R20.1 U3.1 | length 638.4
  Top Layer w20: 2655.75,126.4 J1.4@2703.15,79 J1.4@2703.15,85 ; 2656.15,126.8 v1(2656.15,216) U3.1@2656.15,263.21 ; v1(2738.15,418) 2738.41,417.74 R20.1@2796.65,417.74
  Bottom Layer w20: v1(2656.15,216) 2656.15,366.41 2624.15,398.41 2624.15,433 2648.15,457 2699.15,457 v1(2738.15,418)
"COMMON A": D7.1 J3.1 pad.1@177.05,1776.07 pad.1@177.05,2287.88 pad.1@688.86,1776.07 pad.1@688.86,2287.88 Q2.1 Q2.2 Q2.3 Q3.1 Q3.2 Q3.3 Q8.5 Q8.6 Q8.7 Q8.8 Q12.5 Q12.6 Q12.7 Q12.8 R26.2 R31.1 R32.1 | length 426.5
  Top Layer w25: R26.2@108.15,982.94 108.15,1343.15 155,1390
  other v1: 1253,1354 1303,1354 1353,1354 1403,1354 2024,1354 2074,1354 2124,1354 2174,1354 1253,1394 1303,1394 1353,1394 1403,1394 2024,1394 2074,1394 2124,1394 2174,1394 131.15,1405 191.15,1405 251.15,1405 311.15,1405 371.15,1405 431.15,1405 491.15,1405 551.15,1405 611.15,1405 671.15,1405 731.15,1405 791.15,1405 851.15,1405 911.15,1405 971.15,1405 1031.15,1405 1091.15,1405 1151.15,1405 1211.15,1405 1451.15,1405 1511.15,1405 1571.15,1405 1631.15,1405 1691.15,1405 1751.15,1405 1811.15,1405 1871.15,1405 1931.15,1405 1991.15,1405 2231.15,1405 2291.15,1405 2351.15,1405 2411.15,1405 2471.15,1405 1253,1434 1303,1434 1353,1434 1403,1434 2024,1434 2074,1434 2124,1434 2174,1434 161.15,1465 221.15,1465 281.15,1465 341.15,1465 401.15,1465 461.15,1465 521.15,1465 581.15,1465 641.15,1465 701.15,1465 761.15,1465 821.15,1465 881.15,1465 941.15,1465 1001.15,1465 1061.15,1465 1121.15,1465 1181.15,1465 1481.15,1465 1541.15,1465 1601.15,1465 1661.15,1465 1901.15,1465 1961.15,1465 2201.15,1465 2261.15,1465 2321.15,1465 2381.15,1465 2441.15,1465 2501.15,1465 1253,1478 1303,1478 1353,1478 1403,1478 2024,1478 2074,1478 2124,1478 2174,1478 131.15,1525 191.15,1525 251.15,1525 311.15,1525 371.15,1525 431.15,1525 491.15,1525 551.15,1525 611.15,1525 671.15,1525 731.15,1525 791.15,1525 851.15,1525 911.15,1525 971.15,1525 1031.15,1525 1091.15,1525 1151.15,1525 1211.15,1525 1271.15,1525 1331.15,1525 1391.15,1525 1451.15,1525 1511.15,1525 1571.15,1525 1631.15,1525 1691.15,1525 1931.15,1525 1991.15,1525 2051.15,1525 2111.15,1525 2171.15,1525 2231.15,1525 2291.15,1525 2351.15,1525 2411.15,1525 2471.15,1525 161.15,1585 221.15,1585 281.15,1585 341.15,1585 401.15,1585 461.15,1585 521.15,1585 581.15,1585 641.15,1585 701.15,1585 761.15,1585 821.15,1585 881.15,1585 941.15,1585 1001.15,1585 1061.15,1585 1121.15,1585 1181.15,1585 1241.15,1585 1301.15,1585 1361.15,1585 1421.15,1585 1481.15,1585 1541.15,1585 1601.15,1585 1661.15,1585 1901.15,1585 1961.15,1585 2021.15,1585 2081.15,1585 2141.15,1585 2201.15,1585 2261.15,1585 2321.15,1585 2381.15,1585 2441.15,1585 2501.15,1585 131.15,1645 191.15,1645 251.15,1645 311.15,1645 371.15,1645 431.15,1645 491.15,1645 551.15,1645 611.15,1645 671.15,1645 731.15,1645 791.15,1645 851.15,1645 911.15,1645 971.15,1645 1031.15,1645 1091.15,1645 1151.15,1645 1211.15,1645 1271.15,1645 1331.15,1645 1391.15,1645 1451.15,1645 1511.15,1645 1571.15,1645 1631.15,1645 1691.15,1645 1751.15,1645 1811.15,1645 1871.15,1645 1931.15,1645 1991.15,1645 2051.15,1645 2111.15,1645 2171.15,1645 2231.15,1645 2291.15,1645 2351.15,1645 2411.15,1645 2471.15,1645 221.15,1705 281.15,1705 341.15,1705 401.15,1705 461.15,1705 521.15,1705 581.15,1705 641.15,1705 761.15,1705 821.15,1705 881.15,1705 941.15,1705 1001.15,1705 1061.15,1705 1121.15,1705 1181.15,1705 1241.15,1705 1301.15,1705 1361.15,1705 1421.15,1705 1481.15,1705 1541.15,1705 1601.15,1705 1661.15,1705 1721.15,1705 1781.15,1705 1841.15,1705 1901.15,1705 1961.15,1705 2021.15,1705 2081.15,1705 2141.15,1705 2201.15,1705 2261.15,1705 2321.15,1705 2381.15,1705 2441.15,1705 2501.15,1705 791.15,1765 851.15,1765 911.15,1765 971.15,1765 1031.15,1765 1091.15,1765 1151.15,1765 1211.15,1765 1271.15,1765 1331.15,1765 1391.15,1765 1451.15,1765 1511.15,1765 1571.15,1765 1631.15,1765 1691.15,1765 1751.15,1765 1811.15,1765 1871.15,1765 1931.15,1765 1991.15,1765 2051.15,1765 2111.15,1765 2171.15,1765 2231.15,1765 2291.15,1765 2351.15,1765 2411.15,1765 2471.15,1765 341.15,1825 521.15,1825 761.15,1825 821.15,1825 881.15,1825 941.15,1825 1001.15,1825 1061.15,1825 1121.15,1825 1181.15,1825 1241.15,1825 1301.15,1825 1361.15,1825 1421.15,1825 1481.15,1825 1541.15,1825 1601.15,1825 1661.15,1825 1721.15,1825 1781.15,1825 1841.15,1825 1901.15,1825 1961.15,1825 2021.15,1825 2081.15,1825 2141.15,1825 2201.15,1825 2261.15,1825 2321.15,1825 2381.15,1825 2441.15,1825 2501.15,1825 251.15,1885 311.15,1885 371.15,1885 431.15,1885 491.15,1885 551.15,1885 611.15,1885 791.15,1885 851.15,1885 911.15,1885 971.15,1885 1031.15,1885 1091.15,1885 1151.15,1885 1211.15,1885 1271.15,1885 1331.15,1885 1391.15,1885 1451.15,1885 1511.15,1885 1571.15,1885 1631.15,1885 1691.15,1885 1751.15,1885 1811.15,1885 1871.15,1885 1931.15,1885 1991.15,1885 2051.15,1885 2111.15,1885 2171.15,1885 2231.15,1885 2291.15,1885 2351.15,1885 2411.15,1885 2471.15,1885 281.15,1945 341.15,1945 401.15,1945 461.15,1945 521.15,1945 581.15,1945 761.15,1945 821.15,1945 881.15,1945 941.15,1945 1001.15,1945 1061.15,1945 1121.15,1945 1181.15,1945 1241.15,1945 1301.15,1945 1361.15,1945 1421.15,1945 1481.15,1945 1541.15,1945 1601.15,1945 1661.15,1945 1721.15,1945 1781.15,1945 1841.15,1945 1901.15,1945 1961.15,1945 2021.15,1945 2081.15,1945 2141.15,1945 2201.15,1945 2261.15,1945 2321.15,1945 2381.15,1945 2441.15,1945 2501.15,1945 251.15,2005 311.15,2005 371.15,2005 431.15,2005 491.15,2005 551.15,2005 611.15,2005 791.15,2005 851.15,2005 911.15,2005 971.15,2005 1031.15,2005 1091.15,2005 1151.15,2005 1211.15,2005 1271.15,2005 1331.15,2005 1391.15,2005 1451.15,2005 1511.15,2005 1571.15,2005 1631.15,2005 1691.15,2005 1751.15,2005 1811.15,2005 1871.15,2005 1931.15,2005 1991.15,2005 2051.15,2005 2111.15,2005 2171.15,2005 2231.15,2005 2291.15,2005 2351.15,2005 2411.15,2005 2471.15,2005 281.15,2065 341.15,2065 401.15,2065 461.15,2065 521.15,2065 581.15,2065 761.15,2065 821.15,2065 881.15,2065 941.15,2065 1001.15,2065 1061.15,2065 1121.15,2065 1181.15,2065 1241.15,2065 1301.15,2065 1361.15,2065 1421.15,2065 1481.15,2065 1541.15,2065 1601.15,2065 1661.15,2065 1721.15,2065 1781.15,2065 1841.15,2065 1901.15,2065 1961.15,2065 2021.15,2065 2081.15,2065 2141.15,2065 2201.15,2065 2261.15,2065 2321.15,2065 2381.15,2065 2441.15,2065 2501.15,2065 251.15,2125 311.15,2125 371.15,2125 431.15,2125 491.15,2125 551.15,2125 611.15,2125 791.15,2125 851.15,2125 911.15,2125 971.15,2125 1031.15,2125 1091.15,2125 1151.15,2125 1211.15,2125 1271.15,2125 1331.15,2125 1391.15,2125 1451.15,2125 1511.15,2125 1571.15,2125 1631.15,2125 1691.15,2125 1751.15,2125 1811.15,2125 1871.15,2125 1931.15,2125 1991.15,2125 2051.15,2125 2111.15,2125 2171.15,2125 2231.15,2125 2291.15,2125 2351.15,2125 2411.15,2125 2471.15,2125 281.15,2185 341.15,2185 401.15,2185 461.15,2185 521.15,2185 581.15,2185 761.15,2185 821.15,2185 881.15,2185 941.15,2185 1001.15,2185 1061.15,2185 1121.15,2185 1181.15,2185 1241.15,2185 1301.15,2185 1361.15,2185 1421.15,2185 1481.15,2185 1541.15,2185 1601.15,2185 1661.15,2185 1721.15,2185 1781.15,2185 1841.15,2185 1901.15,2185 1961.15,2185 2021.15,2185 2081.15,2185 2141.15,2185 2201.15,2185 2261.15,2185 2321.15,2185 2381.15,2185 2441.15,2185 2501.15,2185 791.15,2245 851.15,2245 911.15,2245 971.15,2245 1031.15,2245 1091.15,2245 1151.15,2245 1211.15,2245 1271.15,2245 1331.15,2245 1391.15,2245 1451.15,2245 1511.15,2245 1571.15,2245 1631.15,2245 1691.15,2245 1751.15,2245 1811.15,2245 1871.15,2245 1931.15,2245 1991.15,2245 2051.15,2245 2111.15,2245 2171.15,2245 2231.15,2245 2291.15,2245 2351.15,2245 2411.15,2245 2471.15,2245 821.15,2305 881.15,2305 941.15,2305 1001.15,2305 1061.15,2305 1121.15,2305 1181.15,2305 1241.15,2305 1301.15,2305 1361.15,2305 1421.15,2305 1481.15,2305 1541.15,2305 1601.15,2305 1661.15,2305 1721.15,2305 1781.15,2305 1841.15,2305 1901.15,2305 1961.15,2305 2021.15,2305 2081.15,2305 2141.15,2305 2201.15,2305 2261.15,2305 2321.15,2305 2381.15,2305 2441.15,2305 2501.15,2305 131.15,2365 251.15,2365 311.15,2365 371.15,2365 431.15,2365 491.15,2365 551.15,2365 611.15,2365 731.15,2365 791.15,2365 851.15,2365 911.15,2365 971.15,2365 1031.15,2365 1091.15,2365 1151.15,2365 1211.15,2365 1271.15,2365 1331.15,2365 1691.15,2365 1751.15,2365 1811.15,2365 1871.15,2365 1931.15,2365 1991.15,2365 2051.15,2365 2111.15,2365 2411.15,2365 2471.15,2365 161.15,2425 221.15,2425 281.15,2425 341.15,2425 401.15,2425 461.15,2425 521.15,2425 581.15,2425 641.15,2425 701.15,2425 761.15,2425 821.15,2425 881.15,2425 941.15,2425 1001.15,2425 1061.15,2425 1121.15,2425 1181.15,2425 1241.15,2425 1301.15,2425 1661.15,2425 1721.15,2425 1781.15,2425 1841.15,2425 1901.15,2425 1961.15,2425 2021.15,2425 2081.15,2425 2441.15,2425 2501.15,2425 131.15,2485 191.15,2485 251.15,2485 311.15,2485 371.15,2485 431.15,2485 491.15,2485 551.15,2485 611.15,2485 671.15,2485 731.15,2485 791.15,2485 851.15,2485 911.15,2485 971.15,2485 1031.15,2485 1091.15,2485 1151.15,2485 1211.15,2485 1271.15,2485 1331.15,2485 1691.15,2485 1751.15,2485 1811.15,2485 1871.15,2485 1931.15,2485 1991.15,2485 2051.15,2485 2111.15,2485 2411.15,2485 2471.15,2485 161.15,2545 221.15,2545 281.15,2545 341.15,2545 401.15,2545 461.15,2545 521.15,2545 581.15,2545 641.15,2545 701.15,2545 761.15,2545 821.15,2545 881.15,2545 941.15,2545 1001.15,2545 1061.15,2545 1121.15,2545 1181.15,2545 1661.15,2545 1721.15,2545 1781.15,2545 1841.15,2545 1901.15,2545 1961.15,2545 2441.15,2545 2501.15,2545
